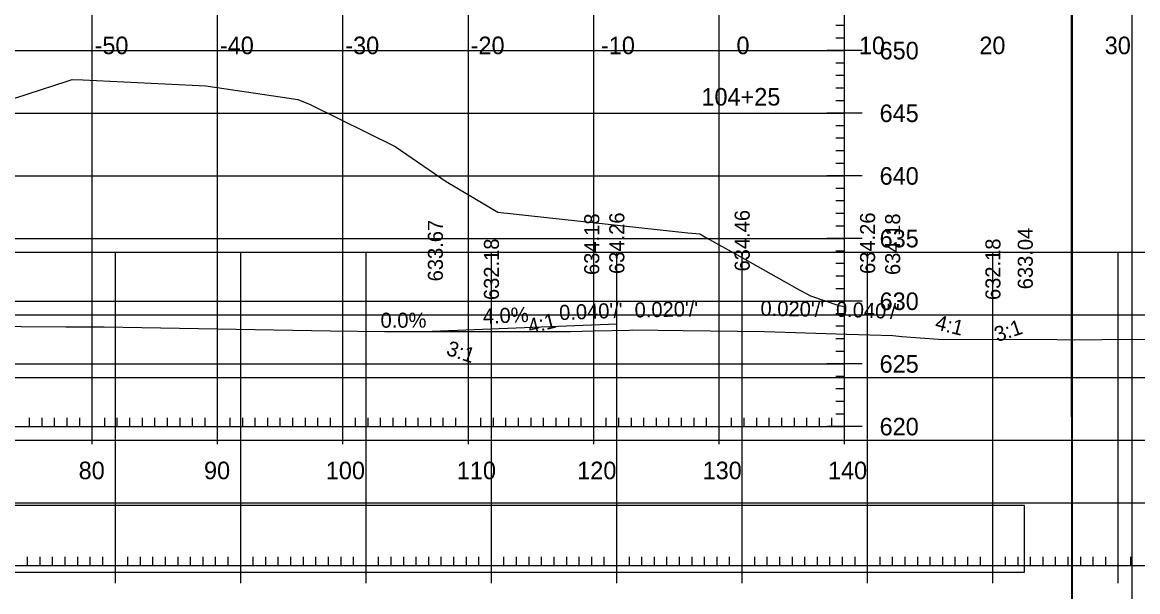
# Model space of a CAD drawing. Extents: x 1381471 to 1382703, y 370300 to 371487.
# Drawn here: x 1382079.2 to 1382168.2, y 371078.4 to 371123.8 of the extents above; entities that cross this region are included whole.
import ezdxf

# ---------------------------------------------------------------- set-up
doc = ezdxf.new("R2010")
doc.units = 0
for name, color, linetype in [('Level 18', 7, 'Continuous'), ('Level 22', 7, 'Continuous'), ('Level 26', 7, 'Continuous'), ('Level 4', 7, 'Continuous'), ('Level 45', 7, 'Continuous'), ('Level 5', 7, 'Continuous'), ('Level 6', 7, 'Continuous')]:
    doc.layers.add(name, color=color, linetype=linetype)

msp = doc.modelspace()

# ---------------------------------------------------------------- linework, layer by layer
at = {"layer": 'Level 18'}
msp.add_lwpolyline([(1382076.514, 371117.092), (1382082.781, 371119.114), (1382083.171, 371119.238), (1382084.019, 371119.2), (1382093.826, 371118.742), (1382099.945, 371117.824), (1382101.162, 371117.651), (1382102.155, 371117.25), (1382108.925, 371113.883), (1382112.991, 371111.095), (1382117.13, 371108.657), (1382132.284, 371107.011), (1382133.244, 371106.914), (1382133.768, 371106.6), (1382136.208, 371105.252), (1382140.961, 371102.567), (1382142.074, 371101.972), (1382144.324, 371101.216), (1382144.772, 371101.115)], dxfattribs=at)
at = {"layer": 'Level 22'}
for p, q in [((1382084.772, 371091.544), (1382084.772, 371126.544)), ((1382094.772, 371091.544), (1382094.772, 371126.544)), ((1382104.772, 371091.544), (1382104.772, 371126.544)), ((1382114.772, 371091.544), (1382114.772, 371126.544)), ((1382124.772, 371091.544), (1382124.772, 371126.544)), ((1382134.772, 371091.544), (1382134.772, 371126.544)), ((1382144.772, 371091.544), (1382144.772, 371126.544)), ((1381864.772, 371121.544), (1382144.772, 371121.544)), ((1381864.772, 371116.544), (1382144.772, 371116.544)), ((1381864.772, 371111.544), (1382144.772, 371111.544)), ((1381864.772, 371106.544), (1382144.772, 371106.544)), ((1381864.772, 371101.544), (1382144.772, 371101.544)), ((1381864.772, 371096.544), (1382144.772, 371096.544)), ((1381864.772, 371091.544), (1382144.772, 371091.544))]:
    msp.add_line(p, q, dxfattribs=at)
at = {"layer": 'Level 26'}
for points in [[(1381834.365, 371187.641), (1382167.705, 371187.641), (1382167.705, 370974.304), (1381834.365, 370974.304)], [(1382080.692, 371183.746), (1382100.312, 371183.746), (1382100.312, 371173.866), (1382116.424, 371173.866), (1382139.624, 371173.866), (1382139.624, 371141.196), (1382162.831, 371141.196), (1382162.952, 370978.286), (1381846.772, 370978.286), (1381846.772, 371183.746)]]:
    msp.add_lwpolyline(points, close=True, dxfattribs=at)
at = {"layer": 'Level 4'}
for p, q in [((1382144.772, 371091.544), (1382144.772, 371126.544)), ((1382144.772, 371123.544), (1382144.072, 371123.544)), ((1382144.772, 371122.544), (1382144.072, 371122.544)), ((1382146.172, 371121.544), (1382143.372, 371121.544)), ((1382144.772, 371120.544), (1382144.072, 371120.544)), ((1382144.772, 371119.544), (1382144.072, 371119.544)), ((1382144.772, 371118.544), (1382144.072, 371118.544)), ((1382144.772, 371117.544), (1382144.072, 371117.544)), ((1382146.172, 371116.544), (1382143.372, 371116.544)), ((1382144.772, 371115.544), (1382144.072, 371115.544)), ((1382144.772, 371114.544), (1382144.072, 371114.544)), ((1382144.772, 371113.544), (1382144.072, 371113.544)), ((1382144.772, 371112.544), (1382144.072, 371112.544)), ((1382146.172, 371111.544), (1382143.372, 371111.544)), ((1382144.772, 371110.544), (1382144.072, 371110.544)), ((1382144.772, 371109.544), (1382144.072, 371109.544)), ((1382144.772, 371108.544), (1382144.072, 371108.544)), ((1382144.772, 371107.544), (1382144.072, 371107.544)), ((1382146.172, 371106.544), (1382143.372, 371106.544)), ((1382144.772, 371105.544), (1382144.072, 371105.544)), ((1382144.772, 371104.544), (1382144.072, 371104.544)), ((1382144.772, 371103.544), (1382144.072, 371103.544)), ((1382144.772, 371102.544), (1382144.072, 371102.544)), ((1382146.172, 371101.544), (1382143.372, 371101.544)), ((1382144.772, 371100.544), (1382144.072, 371100.544)), ((1382144.772, 371099.544), (1382144.072, 371099.544)), ((1382144.772, 371098.544), (1382144.072, 371098.544)), ((1382144.772, 371097.544), (1382144.072, 371097.544)), ((1382146.172, 371096.544), (1382143.372, 371096.544)), ((1382144.772, 371095.544), (1382144.072, 371095.544)), ((1382144.772, 371094.544), (1382144.072, 371094.544)), ((1382144.772, 371093.544), (1382144.072, 371093.544)), ((1382084.772, 371090.144), (1382084.772, 371092.944)), ((1382094.772, 371090.144), (1382094.772, 371092.944)), ((1382104.772, 371090.144), (1382104.772, 371092.944)), ((1382114.772, 371090.144), (1382114.772, 371092.944)), ((1382124.772, 371090.144), (1382124.772, 371092.944)), ((1382134.772, 371090.144), (1382134.772, 371092.944)), ((1382144.772, 371092.544), (1382144.072, 371092.544)), ((1382144.772, 371090.144), (1382144.772, 371092.944)), ((1382079.772, 371091.544), (1382079.772, 371092.244)), ((1382080.772, 371091.544), (1382080.772, 371092.244)), ((1382081.772, 371091.544), (1382081.772, 371092.244)), ((1382082.772, 371091.544), (1382082.772, 371092.244)), ((1382083.772, 371091.544), (1382083.772, 371092.244)), ((1382085.772, 371091.544), (1382085.772, 371092.244)), ((1382086.772, 371091.544), (1382086.772, 371092.244)), ((1382087.772, 371091.544), (1382087.772, 371092.244)), ((1382088.772, 371091.544), (1382088.772, 371092.244)), ((1382089.772, 371091.544), (1382089.772, 371092.244)), ((1382090.772, 371091.544), (1382090.772, 371092.244)), ((1382091.772, 371091.544), (1382091.772, 371092.244)), ((1382092.772, 371091.544), (1382092.772, 371092.244)), ((1382093.772, 371091.544), (1382093.772, 371092.244)), ((1382095.772, 371091.544), (1382095.772, 371092.244)), ((1382096.772, 371091.544), (1382096.772, 371092.244)), ((1382097.772, 371091.544), (1382097.772, 371092.244)), ((1382098.772, 371091.544), (1382098.772, 371092.244)), ((1382099.772, 371091.544), (1382099.772, 371092.244)), ((1382100.772, 371091.544), (1382100.772, 371092.244)), ((1382101.772, 371091.544), (1382101.772, 371092.244)), ((1382102.772, 371091.544), (1382102.772, 371092.244)), ((1382103.772, 371091.544), (1382103.772, 371092.244)), ((1382105.772, 371091.544), (1382105.772, 371092.244)), ((1382106.772, 371091.544), (1382106.772, 371092.244)), ((1382107.772, 371091.544), (1382107.772, 371092.244)), ((1382108.772, 371091.544), (1382108.772, 371092.244)), ((1382109.772, 371091.544), (1382109.772, 371092.244)), ((1382110.772, 371091.544), (1382110.772, 371092.244)), ((1382111.772, 371091.544), (1382111.772, 371092.244)), ((1382112.772, 371091.544), (1382112.772, 371092.244)), ((1382113.772, 371091.544), (1382113.772, 371092.244)), ((1382115.772, 371091.544), (1382115.772, 371092.244)), ((1382116.772, 371091.544), (1382116.772, 371092.244)), ((1382117.772, 371091.544), (1382117.772, 371092.244)), ((1382118.772, 371091.544), (1382118.772, 371092.244)), ((1382119.772, 371091.544), (1382119.772, 371092.244)), ((1382120.772, 371091.544), (1382120.772, 371092.244)), ((1382121.772, 371091.544), (1382121.772, 371092.244)), ((1382122.772, 371091.544), (1382122.772, 371092.244)), ((1382123.772, 371091.544), (1382123.772, 371092.244)), ((1382125.772, 371091.544), (1382125.772, 371092.244)), ((1382126.772, 371091.544), (1382126.772, 371092.244)), ((1382127.772, 371091.544), (1382127.772, 371092.244)), ((1382128.772, 371091.544), (1382128.772, 371092.244)), ((1382129.772, 371091.544), (1382129.772, 371092.244)), ((1382130.772, 371091.544), (1382130.772, 371092.244)), ((1382131.772, 371091.544), (1382131.772, 371092.244)), ((1382132.772, 371091.544), (1382132.772, 371092.244)), ((1382133.772, 371091.544), (1382133.772, 371092.244)), ((1382135.772, 371091.544), (1382135.772, 371092.244)), ((1382136.772, 371091.544), (1382136.772, 371092.244)), ((1382137.772, 371091.544), (1382137.772, 371092.244)), ((1382138.772, 371091.544), (1382138.772, 371092.244)), ((1382139.772, 371091.544), (1382139.772, 371092.244)), ((1382140.772, 371091.544), (1382140.772, 371092.244)), ((1382141.772, 371091.544), (1382141.772, 371092.244)), ((1382142.772, 371091.544), (1382142.772, 371092.244)), ((1382143.772, 371091.544), (1382143.772, 371092.244)), ((1381864.772, 371091.544), (1382144.772, 371091.544)), ((1382146.172, 371091.544), (1382143.372, 371091.544))]:
    msp.add_line(p, q, dxfattribs=at)
at = {"layer": 'Level 45'}
for p, q in [((1381996.613, 371105.458), (1382276.613, 371105.458)), ((1382086.613, 371080.458), (1382086.613, 371105.458)), ((1382096.613, 371080.458), (1382096.613, 371105.458)), ((1382106.613, 371080.458), (1382106.613, 371105.458)), ((1382116.613, 371080.458), (1382116.613, 371105.458)), ((1382126.613, 371080.458), (1382126.613, 371105.458)), ((1382136.613, 371080.458), (1382136.613, 371105.458)), ((1382146.613, 371080.458), (1382146.613, 371105.458)), ((1382156.613, 371080.458), (1382156.613, 371105.458)), ((1382166.613, 371080.458), (1382166.613, 371105.458)), ((1381996.613, 371100.458), (1382276.613, 371100.458)), ((1382126.613, 371099.719), (1382111.895, 371099.13)), ((1382108.12, 371099.13), (1382111.895, 371099.13)), ((1381996.613, 371095.458), (1382276.613, 371095.458)), ((1381996.613, 371090.458), (1382276.613, 371090.458)), ((1381996.613, 371085.458), (1382276.613, 371085.458)), ((1382086.613, 371079.058), (1382086.613, 371081.858)), ((1382096.613, 371079.058), (1382096.613, 371081.858)), ((1382106.613, 371079.058), (1382106.613, 371081.858)), ((1382116.613, 371079.058), (1382116.613, 371081.858)), ((1382126.613, 371079.058), (1382126.613, 371081.858)), ((1382136.613, 371079.058), (1382136.613, 371081.858)), ((1382146.613, 371079.058), (1382146.613, 371081.858)), ((1382156.613, 371079.058), (1382156.613, 371081.858)), ((1382166.613, 371079.058), (1382166.613, 371081.858)), ((1382079.613, 371080.458), (1382079.613, 371081.158)), ((1382080.613, 371080.458), (1382080.613, 371081.158)), ((1382081.613, 371080.458), (1382081.613, 371081.158)), ((1382082.613, 371080.458), (1382082.613, 371081.158)), ((1382083.613, 371080.458), (1382083.613, 371081.158)), ((1382084.613, 371080.458), (1382084.613, 371081.158)), ((1382085.613, 371080.458), (1382085.613, 371081.158)), ((1382087.613, 371080.458), (1382087.613, 371081.158)), ((1382088.613, 371080.458), (1382088.613, 371081.158)), ((1382089.613, 371080.458), (1382089.613, 371081.158)), ((1382090.613, 371080.458), (1382090.613, 371081.158)), ((1382091.613, 371080.458), (1382091.613, 371081.158)), ((1382092.613, 371080.458), (1382092.613, 371081.158)), ((1382093.613, 371080.458), (1382093.613, 371081.158)), ((1382094.613, 371080.458), (1382094.613, 371081.158)), ((1382095.613, 371080.458), (1382095.613, 371081.158)), ((1382097.613, 371080.458), (1382097.613, 371081.158)), ((1382098.613, 371080.458), (1382098.613, 371081.158)), ((1382099.613, 371080.458), (1382099.613, 371081.158)), ((1382100.613, 371080.458), (1382100.613, 371081.158)), ((1382101.613, 371080.458), (1382101.613, 371081.158)), ((1382102.613, 371080.458), (1382102.613, 371081.158)), ((1382103.613, 371080.458), (1382103.613, 371081.158)), ((1382104.613, 371080.458), (1382104.613, 371081.158)), ((1382105.613, 371080.458), (1382105.613, 371081.158)), ((1382107.613, 371080.458), (1382107.613, 371081.158)), ((1382108.613, 371080.458), (1382108.613, 371081.158)), ((1382109.613, 371080.458), (1382109.613, 371081.158)), ((1382110.613, 371080.458), (1382110.613, 371081.158)), ((1382111.613, 371080.458), (1382111.613, 371081.158)), ((1382112.613, 371080.458), (1382112.613, 371081.158)), ((1382113.613, 371080.458), (1382113.613, 371081.158)), ((1382114.613, 371080.458), (1382114.613, 371081.158)), ((1382115.613, 371080.458), (1382115.613, 371081.158)), ((1382117.613, 371080.458), (1382117.613, 371081.158)), ((1382118.613, 371080.458), (1382118.613, 371081.158)), ((1382119.613, 371080.458), (1382119.613, 371081.158)), ((1382120.613, 371080.458), (1382120.613, 371081.158)), ((1382121.613, 371080.458), (1382121.613, 371081.158)), ((1382122.613, 371080.458), (1382122.613, 371081.158)), ((1382123.613, 371080.458), (1382123.613, 371081.158)), ((1382124.613, 371080.458), (1382124.613, 371081.158)), ((1382125.613, 371080.458), (1382125.613, 371081.158)), ((1382127.613, 371080.458), (1382127.613, 371081.158)), ((1382128.613, 371080.458), (1382128.613, 371081.158)), ((1382129.613, 371080.458), (1382129.613, 371081.158)), ((1382130.613, 371080.458), (1382130.613, 371081.158)), ((1382131.613, 371080.458), (1382131.613, 371081.158)), ((1382132.613, 371080.458), (1382132.613, 371081.158)), ((1382133.613, 371080.458), (1382133.613, 371081.158)), ((1382134.613, 371080.458), (1382134.613, 371081.158)), ((1382135.613, 371080.458), (1382135.613, 371081.158)), ((1382137.613, 371080.458), (1382137.613, 371081.158)), ((1382138.613, 371080.458), (1382138.613, 371081.158)), ((1382139.613, 371080.458), (1382139.613, 371081.158)), ((1382140.613, 371080.458), (1382140.613, 371081.158)), ((1382141.613, 371080.458), (1382141.613, 371081.158)), ((1382142.613, 371080.458), (1382142.613, 371081.158)), ((1382143.613, 371080.458), (1382143.613, 371081.158)), ((1382144.613, 371080.458), (1382144.613, 371081.158)), ((1382145.613, 371080.458), (1382145.613, 371081.158)), ((1382147.613, 371080.458), (1382147.613, 371081.158)), ((1382148.613, 371080.458), (1382148.613, 371081.158)), ((1382149.613, 371080.458), (1382149.613, 371081.158)), ((1382150.613, 371080.458), (1382150.613, 371081.158)), ((1382151.613, 371080.458), (1382151.613, 371081.158)), ((1382152.613, 371080.458), (1382152.613, 371081.158)), ((1382153.613, 371080.458), (1382153.613, 371081.158)), ((1382154.613, 371080.458), (1382154.613, 371081.158)), ((1382155.613, 371080.458), (1382155.613, 371081.158)), ((1382157.613, 371080.458), (1382157.613, 371081.158)), ((1382158.613, 371080.458), (1382158.613, 371081.158)), ((1382159.613, 371080.458), (1382159.613, 371081.158)), ((1382160.613, 371080.458), (1382160.613, 371081.158)), ((1382161.613, 371080.458), (1382161.613, 371081.158)), ((1382162.613, 371080.458), (1382162.613, 371081.158)), ((1382163.613, 371080.458), (1382163.613, 371081.158)), ((1382164.613, 371080.458), (1382164.613, 371081.158)), ((1382165.613, 371080.458), (1382165.613, 371081.158)), ((1382167.613, 371080.458), (1382167.613, 371081.158)), ((1381996.613, 371080.458), (1382276.613, 371080.458)), ((1381996.613, 371080.458), (1382276.613, 371080.458))]:
    msp.add_line(p, q, dxfattribs=at)
msp.add_lwpolyline([(1382064.794, 371099.636), (1382082.66, 371099.514), (1382085.71, 371099.506), (1382103.762, 371099.176), (1382108.12, 371099.13), (1382122.914, 371099.131), (1382124.782, 371099.19), (1382127.624, 371099.235), (1382127.902, 371099.256), (1382131.9, 371099.199), (1382138.399, 371099.128), (1382144.949, 371098.909), (1382148.617, 371098.811), (1382149.352, 371098.744), (1382152.259, 371098.531), (1382161.705, 371098.487), (1382163.145, 371098.473), (1382165.297, 371098.504), (1382176.729, 371098.508)], dxfattribs=at)
at = {"layer": 'Level 6'}
msp.add_line((1382162.952, 370978.286), (1382162.952, 371183.746), dxfattribs=at)
msp.add_lwpolyline([(1381850.409, 371079.931), (1382159.135, 371079.931), (1382159.135, 371085.253), (1381850.409, 371085.253)], close=True, dxfattribs=at)

# ---------------------------------------------------------------- texts
at = {"layer": 'Level 45'}
for s, p in [('-50', (1382084.954, 371121.258)), ('-40', (1382094.954, 371121.258)), ('-30', (1382104.954, 371121.258)), ('-20', (1382114.954, 371121.258)), ('-10', (1382125.351, 371121.258)), ('0', (1382136.156, 371121.258)), ('10', (1382145.924, 371121.258)), ('20', (1382155.528, 371121.258)), ('30', (1382165.528, 371121.258)), ('104+25', (1382133.361, 371117.158))]:
    msp.add_text(s, height=1.4, dxfattribs=at).set_placement(p)
for s, rotation, p in [('634.26', 90, (1382127.213, 371103.719)), ('634.46', 90, (1382137.213, 371103.919)), ('634.26', 90, (1382147.213, 371103.719)), ('633.67', 90, (1382112.74, 371103.13)), ('634.18', 90, (1382125.213, 371103.639)), ('634.18', 90, (1382149.213, 371103.639)), ('633.04', 90, (1382159.792, 371102.498)), ('632.18', 90, (1382117.213, 371101.639)), ('632.18', 90, (1382157.213, 371101.639)), ("0.040'/'", 2.29061, (1382122.034, 371100.036)), ("0.020'/'", 1.14576, (1382128.042, 371100.248)), ("0.020'/'", 358.85424, (1382138.062, 371100.39)), ("0.040'/'", 357.70939, (1382144.074, 371100.321)), ('0.0%', 0.00643, (1382107.768, 371099.432)), ('4.0%', 2.29061, (1382115.944, 371099.743)), ('4:1', 14.03624, (1382119.685, 371098.922)), ('4:1', 345.96376, (1382151.928, 371099.326)), ('3:1', 18.43493, (1382156.956, 371098.28)), ('3:1', 341.56522, (1382112.929, 371097.295))]:
    msp.add_text(s, height=1.2, rotation=rotation, dxfattribs=at).set_placement(p)
at = {"layer": 'Level 5'}
for s, p in [('650', (1382147.572, 371120.844)), ('645', (1382147.572, 371115.844)), ('640', (1382147.572, 371110.844)), ('635', (1382147.572, 371105.844)), ('630', (1382147.572, 371100.844)), ('625', (1382147.572, 371095.844)), ('620', (1382147.572, 371090.844)), ('80', (1382083.686, 371087.344)), ('90', (1382093.686, 371087.344)), ('100', (1382103.4, 371087.344)), ('110', (1382113.852, 371087.344)), ('120', (1382123.455, 371087.344)), ('130', (1382133.455, 371087.344)), ('140', (1382143.455, 371087.344))]:
    msp.add_text(s, height=1.4, dxfattribs=at).set_placement(p)

doc.saveas('drawing.dxf')
